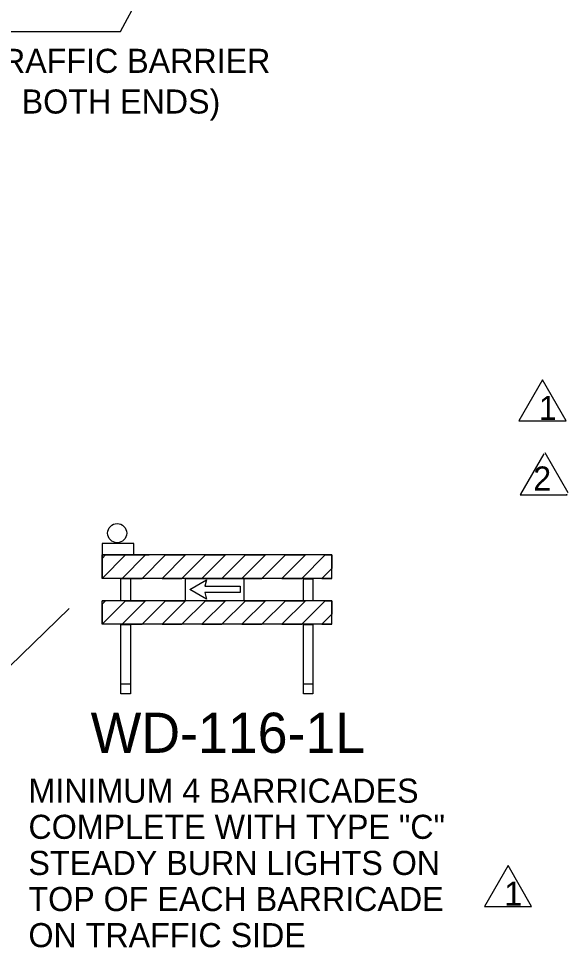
# Model space of a CAD drawing. Extents: x 2179 to 2395, y 134 to 413.
# Drawn here: x 2253.5 to 2286.6, y 308.2 to 364.6 of the extents above; entities that cross this region are included whole.
import ezdxf

# ---------------------------------------------------------------- set-up
doc = ezdxf.new("R2010")
doc.units = 0
for name, color, linetype in [('Level 1', 7, 'Continuous'), ('Level 10', 7, 'Continuous'), ('Level 44', 7, 'Continuous'), ('Level 5', 7, 'Continuous'), ('Level 63', 7, 'Continuous')]:
    doc.layers.add(name, color=color, linetype=linetype)

# ---------------------------------------------------------------- blocks, each defined once
blk = doc.blocks.new('REV1')
at = {"layer": 'Level 1'}
blk.add_lwpolyline([(0.114, 1.689), (-1.305, -0.781), (1.533, -0.781)], close=True, dxfattribs=at)
blk.add_text('1', height=1.448, rotation=360, dxfattribs=at).set_placement((-0.113, -0.724))

msp = doc.modelspace()

# ---------------------------------------------------------------- linework, layer by layer
at = {"layer": 'Level 10'}
for p, q in [((2232.456, 363.851), (2259.582, 363.833)), ((2231.006, 304.399), (2256.495, 329.053))]:
    msp.add_line(p, q, dxfattribs=at)
msp.add_lwpolyline([(2258.477, 332.295), (2260.383, 332.295), (2260.383, 332.987), (2258.477, 332.987)], close=True, dxfattribs=at)
msp.add_circle((2259.384, 333.603), 0.576, dxfattribs=at)
at = {"layer": 'Level 5'}
for p, q in [((2259.582, 363.833), (2263.56, 371.276)), ((2258.469, 332.316), (2272.311, 332.316)), ((2258.477, 330.876), (2258.477, 332.295)), ((2260.747, 332.295), (2261.313, 332.295)), ((2272.319, 330.876), (2272.319, 332.295)), ((2272.319, 330.876), (2258.477, 330.876)), ((2259.612, 330.849), (2259.612, 330.876)), ((2263.53, 330.862), (2267.018, 330.862)), ((2263.53, 330.862), (2267.018, 330.862)), ((2270.617, 330.849), (2270.617, 330.876)), ((2258.477, 328.111), (2258.477, 329.529)), ((2272.319, 329.529), (2258.477, 329.529)), ((2271.184, 329.529), (2270.901, 329.529)), ((2272.319, 328.111), (2272.319, 329.529)), ((2272.319, 328.111), (2258.477, 328.111)), ((2260.179, 324.495), (2259.612, 324.495)), ((2271.184, 324.495), (2270.617, 324.495))]:
    msp.add_line(p, q, dxfattribs=at)
for points in [[(2258.477, 330.876), (2259.895, 332.295), (2258.692, 332.295), (2258.477, 332.08), (2258.477, 330.876)], [(2260.884, 330.876), (2262.302, 332.295), (2261.099, 332.295), (2259.681, 330.876), (2260.884, 330.876)], [(2263.291, 330.876), (2264.709, 332.295), (2263.505, 332.295), (2262.087, 330.876), (2263.291, 330.876)], [(2265.697, 330.876), (2267.116, 332.295), (2265.912, 332.295), (2264.494, 330.876), (2265.697, 330.876)], [(2269.522, 332.295), (2268.319, 332.295), (2266.901, 330.876), (2268.104, 330.876), (2269.522, 332.295)], [(2271.929, 332.295), (2270.727, 332.295), (2269.308, 330.876), (2270.512, 330.876), (2271.929, 332.295)], [(2272.319, 331.481), (2271.715, 330.876), (2272.319, 330.876), (2272.319, 331.481)], [(2258.477, 328.111), (2259.895, 329.529), (2258.692, 329.529), (2258.477, 329.314), (2258.477, 328.111)], [(2260.884, 328.111), (2262.302, 329.529), (2261.099, 329.529), (2259.681, 328.111), (2260.884, 328.111)], [(2263.291, 328.111), (2264.709, 329.529), (2263.505, 329.529), (2262.087, 328.111), (2263.291, 328.111)], [(2265.697, 328.111), (2267.116, 329.529), (2265.912, 329.529), (2264.494, 328.111), (2265.697, 328.111)], [(2269.522, 329.529), (2268.319, 329.529), (2266.901, 328.111), (2268.104, 328.111), (2269.522, 329.529)], [(2271.929, 329.529), (2270.727, 329.529), (2269.308, 328.111), (2270.512, 328.111), (2271.929, 329.529)], [(2272.319, 328.716), (2271.715, 328.111), (2272.319, 328.111), (2272.319, 328.716)]]:
    msp.add_lwpolyline(points, dxfattribs=at)
for points in [[(2259.895, 332.295), (2261.099, 332.295), (2259.681, 330.876), (2258.477, 330.876)], [(2258.692, 332.295), (2258.477, 332.295), (2258.477, 332.08)], [(2262.302, 332.295), (2263.505, 332.295), (2262.087, 330.876), (2260.884, 330.876)], [(2264.709, 332.295), (2265.912, 332.295), (2264.494, 330.876), (2263.291, 330.876)], [(2267.116, 332.295), (2268.319, 332.295), (2266.901, 330.876), (2265.697, 330.876)], [(2269.522, 332.295), (2270.727, 332.295), (2269.308, 330.876), (2268.104, 330.876)], [(2271.929, 332.295), (2272.319, 332.295), (2272.319, 331.481), (2271.715, 330.876), (2270.512, 330.876)], [(2259.612, 330.849), (2260.179, 330.876), (2260.179, 329.529), (2259.612, 329.529)], [(2267.018, 330.862), (2267.018, 329.529), (2263.505, 329.529), (2263.505, 330.862)], [(2266.791, 330.401), (2266.791, 330.027), (2264.664, 330.027), (2264.778, 329.629), (2263.757, 330.214), (2264.778, 330.798), (2264.664, 330.401)], [(2270.617, 330.849), (2271.184, 330.849), (2271.184, 329.529), (2270.617, 329.529)], [(2258.477, 329.529), (2258.692, 329.529), (2258.477, 329.314)], [(2259.895, 329.529), (2261.099, 329.529), (2259.681, 328.111), (2258.477, 328.111)], [(2262.302, 329.529), (2263.505, 329.529), (2262.087, 328.111), (2260.884, 328.111)], [(2264.709, 329.529), (2265.912, 329.529), (2264.494, 328.111), (2263.291, 328.111)], [(2267.116, 329.529), (2268.319, 329.529), (2266.901, 328.111), (2265.697, 328.111)], [(2269.522, 329.529), (2270.727, 329.529), (2269.308, 328.111), (2268.104, 328.111)], [(2271.929, 329.529), (2272.319, 329.529), (2272.319, 328.716), (2271.715, 328.111), (2270.512, 328.111)], [(2259.612, 328.097), (2260.179, 328.097), (2260.179, 323.927), (2259.612, 323.927)], [(2270.617, 328.097), (2271.184, 328.097), (2271.184, 323.927), (2270.617, 323.927)]]:
    msp.add_lwpolyline(points, close=True, dxfattribs=at)
at = {"layer": 'Level 63'}
for points in [[(2285.087, 338.373), (2283.694, 335.948)], [(2286.569, 336.025), (2285.175, 338.45)], [(2283.694, 335.948), (2283.668, 335.903), (2286.507, 335.903), (2286.481, 335.948)]]:
    msp.add_lwpolyline(points, dxfattribs=at)

# ---------------------------------------------------------------- block references
at = {"layer": 'Level 1'}
for p in [(2284.903, 341.148), (2282.824, 311.875)]:
    msp.add_blockref('REV1', p, dxfattribs=at)

# ---------------------------------------------------------------- texts
at = {"layer": 'Level 10'}
for s, height, p in [('TEMPORARY TRAFFIC BARRIER ', 1.451, (2238.429, 361.34)), ('4:1 TAPER (TYP BOTH ENDS)', 1.451, (2238.429, 358.889)), ('WD-116-1L', 2.419, (2257.789, 320.361)), ('MINIMUM 4 BARRICADES', 1.4514, (2254.04, 317.355)), ('COMPLETE WITH TYPE "C" ', 1.4514, (2254.04, 315.179)), ('STEADY BURN LIGHTS ON ', 1.4514, (2254.04, 313.003)), ('TOP OF EACH BARRICADE ', 1.4514, (2254.04, 310.827)), ('ON TRAFFIC SIDE', 1.4514, (2254.04, 308.651))]:
    msp.add_text(s, height=height, dxfattribs=at).set_placement(p)
at = {"layer": 'Level 44'}
msp.add_text('2', height=1.448, rotation=360, dxfattribs=at).set_placement((2284.46, 336.172))

doc.saveas('drawing.dxf')
